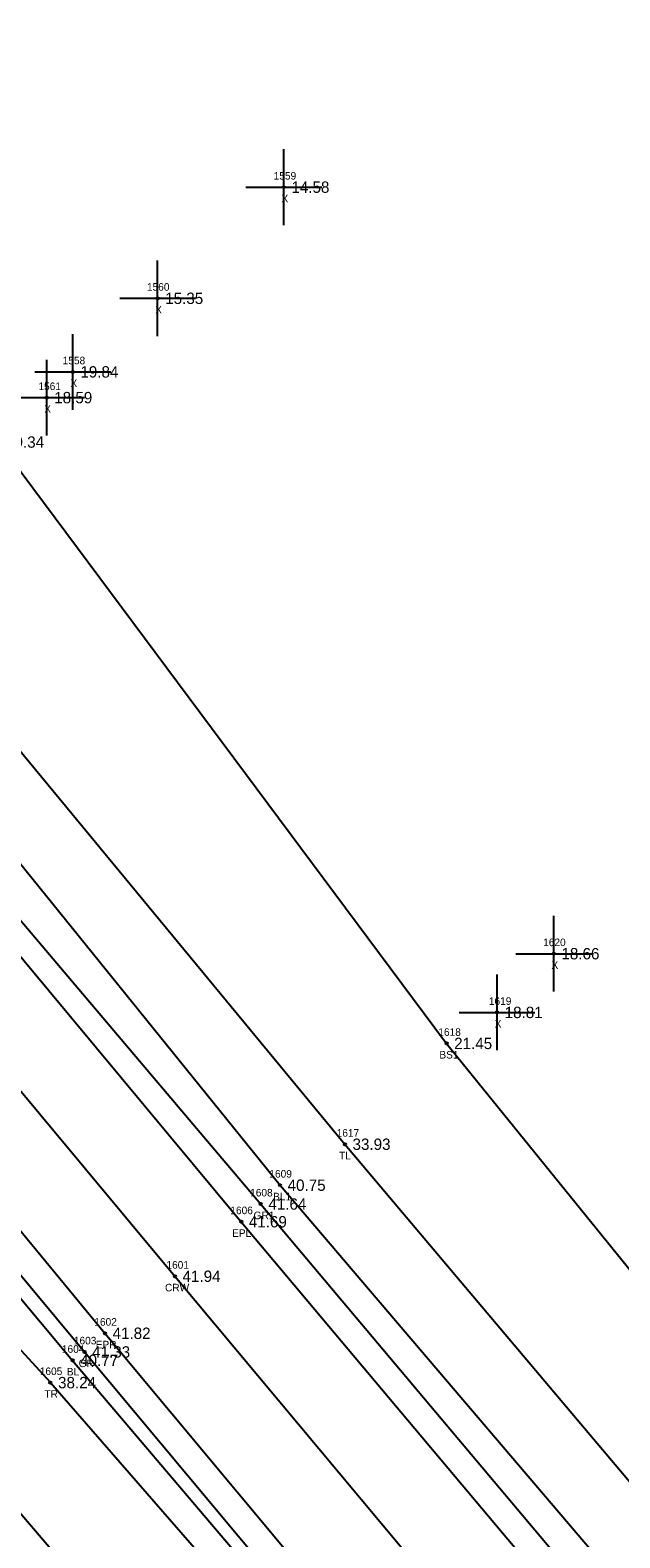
# Model space of a CAD drawing. Extents: x 2042211 to 2045853, y 303080 to 309569.
# Drawn here: x 2043600.8 to 2043678.7, y 305686.3 to 305885.5 of the extents above; entities that cross this region are included whole.
import ezdxf

# ---------------------------------------------------------------- set-up
doc = ezdxf.new("R2010")
doc.units = 0
for name, color, linetype in [('BR_500YR_SCOUR', 7, 'Continuous'), ('RD_DTM_BkLn1', 7, 'Continuous'), ('RD_DTM_BkLn2', 7, 'Continuous'), ('RD_DTM_BkLn_txCode', 7, 'Continuous'), ('RD_EX_GuardRail_txCode', 7, 'Continuous'), ('RD_EX_Misc', 7, 'Continuous'), ('RD_EX_Misc_txCode', 7, 'Continuous'), ('RD_EX_Road', 7, 'Continuous'), ('RD_EX_Road_txCode', 7, 'Continuous'), ('RD_EX_TX_GuardRail_ELEV', 7, 'Continuous'), ('RD_EX_TX_Misc_ELEV', 7, 'Continuous'), ('RD_EX_TX_Road_ELEV', 7, 'Continuous'), ('RD_EX_TX_VEG_ELEV', 7, 'Continuous'), ('RD_EX_VEG_txCode', 7, 'Continuous'), ('RD_HC_Survey_ELEV', 7, 'Continuous'), ('RD_HC_Survey_txCode', 7, 'Continuous'), ('RD_SMD_Locator', 7, 'Continuous')]:
    doc.layers.add(name, color=color, linetype=linetype)

msp = doc.modelspace()

# ---------------------------------------------------------------- linework, layer by layer
at = {"layer": 'BR_500YR_SCOUR'}
for points in [[(2043547.51, 305881.5), (2043539.7, 305861.32), (2043541.74, 305855.07), (2043567.73, 305828.7), (2043642.4, 305738.29), (2043706.88, 305661.84), (2043768.33, 305586.86), (2043834.29, 305506.38), (2043895.63, 305432.16), (2043964.52, 305353.99), (2044012.41, 305288.23), (2044020.96, 305286.08), (2044026.64, 305287.13), (2044039.88, 305282.36)], [(2043536.57, 305840.53), (2043552.74, 305821.73), (2043567.12, 305805.58), (2043586.37, 305783.45), (2043631.29, 305730.39), (2043695.95, 305653.5), (2043733.01, 305610.16)], [(2043521.57, 305819.7), (2043537.59, 305799.24), (2043545.81, 305788.34), (2043545.84, 305788.25), (2043568.41, 305758.48), (2043608.02, 305710.85), (2043672.21, 305633.93), (2043713.59, 305584.16)], [(2043510.52, 305810.42), (2043502.87, 305810.61), (2043504.87, 305802.25), (2043509.11, 305791.37), (2043594.27, 305695.69), (2043658.16, 305620.89), (2043717.86, 305542.89), (2043784.35, 305466.31), (2043848.97, 305392.37), (2043916.01, 305316.79), (2043971.98, 305240.84)], [(2043510.52, 305810.42), (2043528.58, 305788.55), (2043603.52, 305706.8), (2043669.11, 305631.48), (2043746.08, 305529.27), (2043781.83, 305496.01), (2043793.11, 305482.33), (2043857.16, 305399.04), (2043922.61, 305323.93), (2043978.69, 305250.66), (2043978.39, 305246.16), (2043971.98, 305240.84)]]:
    msp.add_lwpolyline(points, dxfattribs=at)
for centre in [(2043642.4, 305738.29), (2043631.29, 305730.39), (2043608.02, 305710.85), (2043603.52, 305706.8)]:
    msp.add_circle(centre, 0.15, dxfattribs=at)
at = {"layer": 'RD_DTM_BkLn1'}
for points in [[(2043537.57, 305841.2), (2043543.07, 305834.82), (2043547.67, 305836.32), (2043557.54, 305825.5), (2043571.92, 305809.49), (2043633.83, 305732.88), (2043699.09, 305656.29), (2043762.93, 305580.55), (2043827.21, 305502.36), (2043888.69, 305425.33), (2043954.53, 305349.45), (2044014.08, 305277.47), (2044018.49, 305276.45), (2044019.61, 305275.44), (2044023.1, 305269.64), (2044024.11, 305264.85), (2044081.02, 305196.95), (2044145.48, 305121.13), (2044210.56, 305044.49), (2044273.6, 304967.95), (2044321.18, 304912.75), (2044337.82, 304895.78)], [(2043528.91, 305830.2), (2043556.35, 305797.19), (2043619.96, 305720.85), (2043684.02, 305644.21), (2043747.98, 305567.9), (2043812.35, 305491.13), (2043876, 305414.64), (2043940.22, 305337.83), (2044003.86, 305261.82), (2044067.88, 305184.94), (2044131, 305108.73), (2044195.62, 305032.03), (2044259.59, 304955.88), (2044323.63, 304879.52), (2044387.48, 304802.4), (2044451.92, 304725.21), (2044515.94, 304648.42), (2044581.15, 304571.52), (2044645.01, 304495.17), (2044708.42, 304418.52), (2044772.84, 304341.13)], [(2043520.73, 305818.77), (2043522.48, 305814.7), (2043519.99, 305810), (2043533.02, 305796.66), (2043535.95, 305795.26), (2043535.95, 305795.26), (2043537.42, 305792.63), (2043539.97, 305790.04), (2043542.8, 305785.93), (2043606.44, 305709.74), (2043671.26, 305633.37), (2043734.82, 305555.69), (2043798.36, 305479.17), (2043862.32, 305402.71)]]:
    msp.add_lwpolyline(points, dxfattribs=at)
at = {"layer": 'RD_DTM_BkLn2'}
msp.add_lwpolyline([(2043547.74, 305884.86), (2043551.89, 305882.53), (2043558.15, 305885.46), (2043596.66, 305831.05), (2043655.82, 305751.61), (2043719.21, 305673.32), (2043779.86, 305593.61), (2043842.41, 305514.12), (2043901.08, 305439), (2043924.64, 305407.41), (2043962.04, 305355.58), (2044016.29, 305283.02), (2044024.42, 305277.9)], dxfattribs=at)
at = {"layer": 'RD_EX_Misc'}
for p, q in [((2043634.33, 305859.72), (2043634.33, 305869.72)), ((2043629.33, 305864.72), (2043639.33, 305864.72)), ((2043617.67, 305845.04), (2043617.67, 305855.04)), ((2043612.67, 305850.04), (2043622.67, 305850.04)), ((2043606.47, 305835.32), (2043606.47, 305845.32)), ((2043603.02, 305831.92), (2043603.02, 305841.92)), ((2043601.47, 305840.32), (2043611.47, 305840.32)), ((2043598.02, 305836.92), (2043608.02, 305836.92)), ((2043669.98, 305758.46), (2043669.98, 305768.46)), ((2043664.98, 305763.46), (2043674.98, 305763.46)), ((2043662.49, 305750.7), (2043662.49, 305760.7)), ((2043657.49, 305755.7), (2043667.49, 305755.7))]:
    msp.add_line(p, q, dxfattribs=at)
at = {"layer": 'RD_EX_Road'}
for points in [[(2043536.39, 305840.18), (2043565.06, 305804.59), (2043628.71, 305728.05), (2043693.07, 305651.37), (2043757.81, 305576.46), (2043821.87, 305499.1), (2043885.81, 305423.07)], [(2043522.11, 305820), (2043547.67, 305789.85), (2043610.72, 305713.32), (2043674.95, 305636.32), (2043738.18, 305559.62), (2043802.42, 305482.71), (2043865.72, 305405.84), (2043929.53, 305328.85), (2043994.13, 305253.28), (2044057.4, 305176.5), (2044121.27, 305100.2), (2044185.29, 305023.54), (2044249.56, 304947.28), (2044313.31, 304870.31), (2044377.09, 304793.29), (2044442, 304716.26), (2044505.92, 304639.55), (2044570.44, 304562.35), (2044634.61, 304485.93), (2044698.46, 304409.27), (2044762.46, 304332.37)]]:
    msp.add_lwpolyline(points, dxfattribs=at)
at = {"layer": 'RD_SMD_Locator'}
for centre in [(2043634.33, 305864.72), (2043617.67, 305850.04), (2043606.47, 305840.32), (2043603.02, 305836.92), (2043669.98, 305763.46), (2043662.49, 305755.7), (2043655.82, 305751.61), (2043633.83, 305732.88), (2043628.71, 305728.05), (2043619.96, 305720.85), (2043610.72, 305713.32), (2043606.44, 305709.74)]:
    msp.add_circle(centre, 0.15, dxfattribs=at)

# ---------------------------------------------------------------- texts
at = {"layer": 'RD_DTM_BkLn_txCode'}
for s, p in [('1618', (2043654.73, 305752.61)), ('BS1', (2043654.87, 305749.61)), ('1609', (2043632.42, 305733.88)), ('BL1', (2043632.91, 305730.88)), ('1604', (2043605.03, 305710.74)), ('BL', (2043605.68, 305707.74))]:
    msp.add_text(s, height=1, dxfattribs=at).set_placement(p)
at = {"layer": 'RD_EX_GuardRail_txCode'}
for s, p in [('1608', (2043629.88, 305731.39)), ('GR1', (2043630.34, 305728.39)), ('1603', (2043606.61, 305711.85)), ('GR', (2043607.24, 305708.85))]:
    msp.add_text(s, height=1, dxfattribs=at).set_placement(p)
at = {"layer": 'RD_EX_Misc_txCode'}
for s, p in [('1559', (2043632.99, 305865.72)), ('X', (2043634.02, 305862.72)), ('1560', (2043616.26, 305851.04)), ('X', (2043617.35, 305848.04)), ('1558', (2043605.13, 305841.32)), ('1561', (2043601.93, 305837.92)), ('X', (2043606.16, 305838.32)), ('X', (2043602.7, 305834.92)), ('1620', (2043668.57, 305764.46)), ('X', (2043669.67, 305761.46)), ('1619', (2043661.4, 305756.7)), ('X', (2043662.17, 305753.7))]:
    msp.add_text(s, height=1, dxfattribs=at).set_placement(p)
at = {"layer": 'RD_EX_Road_txCode'}
for s, p in [('1606', (2043627.27, 305729.05)), ('EPL', (2043627.5, 305726.05)), ('1602', (2043609.31, 305714.32)), ('EPR', (2043609.49, 305711.32))]:
    msp.add_text(s, height=1, dxfattribs=at).set_placement(p)
at = {"layer": 'RD_EX_TX_GuardRail_ELEV'}
for s, p in [('41.64', (2043632.29, 305729.64)), ('41.33', (2043609.02, 305710.1))]:
    msp.add_text(s, height=1.5, dxfattribs=at).set_placement(p)
at = {"layer": 'RD_EX_TX_Misc_ELEV'}
for s, p in [('14.58', (2043635.33, 305863.97)), ('15.35', (2043618.67, 305849.29)), ('19.84', (2043607.47, 305839.57)), ('18.59', (2043604.02, 305836.17)), ('19.34', (2043597.66, 305830.3)), ('18.66', (2043670.98, 305762.71)), ('18.81', (2043663.49, 305754.95)), ('21.45', (2043656.82, 305750.86)), ('40.75', (2043634.83, 305732.13)), ('40.77', (2043607.44, 305708.99))]:
    msp.add_text(s, height=1.5, dxfattribs=at).set_placement(p)
at = {"layer": 'RD_EX_TX_Road_ELEV'}
for s, p in [('41.69', (2043629.71, 305727.3)), ('41.82', (2043611.72, 305712.57))]:
    msp.add_text(s, height=1.5, dxfattribs=at).set_placement(p)
at = {"layer": 'RD_EX_TX_VEG_ELEV'}
for s, p in [('33.93', (2043643.4, 305737.54)), ('38.24', (2043604.52, 305706.05))]:
    msp.add_text(s, height=1.5, dxfattribs=at).set_placement(p)
at = {"layer": 'RD_EX_VEG_txCode'}
for s, p in [('1617', (2043641.31, 305739.29)), ('TL', (2043641.63, 305736.29)), ('1605', (2043602.11, 305707.8)), ('TR', (2043602.73, 305704.8))]:
    msp.add_text(s, height=1, dxfattribs=at).set_placement(p)
at = {"layer": 'RD_HC_Survey_ELEV'}
msp.add_text('41.94', height=1.5, dxfattribs=at).set_placement((2043620.96, 305720.1))
at = {"layer": 'RD_HC_Survey_txCode'}
for s, p in [('1601', (2043618.83, 305721.85)), ('CRW', (2043618.64, 305718.85))]:
    msp.add_text(s, height=1, dxfattribs=at).set_placement(p)

doc.saveas('drawing.dxf')
